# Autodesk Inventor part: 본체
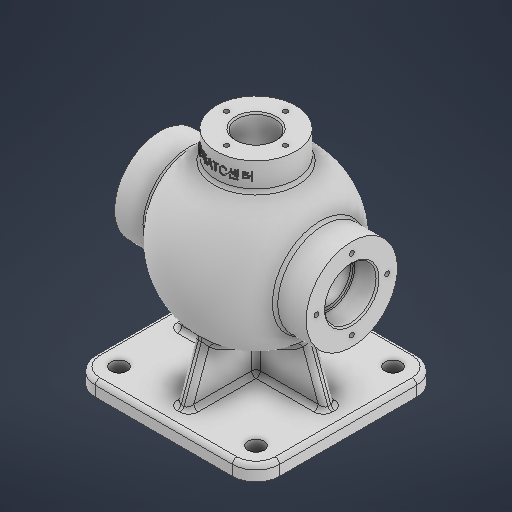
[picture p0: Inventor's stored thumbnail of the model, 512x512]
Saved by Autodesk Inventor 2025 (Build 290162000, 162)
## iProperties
Created: 2025-08
Part Number: 본체
Material: 일반
Document SubType Name: Modeling
Designer: infra14
Density: 1 g/cm^3
Appearance: 기본값
Author: infra14
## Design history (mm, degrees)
sketch "스케치1"
  geometry: L1 (-46.5, 62.5)-(46.5, 62.5); L2 (62.5, 46.5)-(62.5, -46.5); L3 (46.5, -62.5)-(-46.5, -62.5); L4 (-62.5, -46.5)-(-62.5, 46.5); L5 (-62.5, 62.5)-(62.5, -62.5); L6 (62.5, 62.5)-(-62.5, -62.5); A1 r 16 centre (46.5, 46.5) between (62.5, 46.5) and (46.5, 62.5); A2 r 16 centre (46.5, -46.5) between (46.5, -62.5) and (62.5, -46.5); A3 r 16 centre (-46.5, -46.5) between (-62.5, -46.5) and (-46.5, -62.5); A4 r 16 centre (-46.5, 46.5) between (-46.5, 62.5) and (-62.5, 46.5); 1 further point
  constraints: 12 end point, 8 point on circle, 8 point on line, 8 tangent, 4 centre point, 3 equal radius, 2 midpoint, 2 parallel, 1 horizontal, 1 perpendicular
  dimensions: "d0" = 125 distance of L6.end L5.start; "d1" = 125 distance of L5.end L6.end; "d2" = 16 radius of A1
extrude "돌출1" new body sketch "스케치1" distance "d3" = 10; taper "d4" = 0 deg
sketch "스케치2"
  geometry: L1 (46.5, 0)-(-46.5, 0) reference; L2 (65, 54)-(-65, 54); L3 (-65, 54)-(-65, 116); L4 (-65, 116)-(65, 116); L5 (65, 116)-(65, 54); L6 (65, 54)-(-65, 116); L7 (-65, 54)-(65, 116); L8 (65, 85)-(-65, 85); C1 r 54 at (0, 85); C2 r 44 at (0, 85); 6 further points
  constraints: 14 end point, 5 midpoint, 2 centre point, 2 parallel, 1 coincident, 1 horizontal, 1 perpendicular, 1 vertical alignment
  dimensions: "d5" = 108 diameter of C1; "d6" = 88 diameter of C2; "d7" = 85 distance from line of L1 C1.centre; "d8" = 62 distance between parallel lines of L2 L4; "d9" = 130 distance between parallel lines of L5 L3
revolve "회전1" stored, may be unused: angle "d10" = 90 deg
sketch "스케치3"
  geometry: L1 (-46.5, 10)-(46.5, 10) reference; L2 (50.5, 10)-(30.482, 65); L3 (30.482, 65)-(-30.482, 65); L4 (-30.482, 65)-(-50.5, 10); L5 (62.5, 0)-(62.5, 10) reference; L6 (-62.5, 0)-(-62.5, 10) reference; L7 (-46.5, 0)-(46.5, 0) reference; 1 further point
  constraints: 6 end point, 2 point on line, 1 parallel
  dimensions: "d11" = 12 distance from line of L5 L2.start; "d12" = 12 distance from line of L6 L4.end; "d13" = 20 deg angle of L5 L2; "d14" = 20 deg angle of L6 L4; "d15" = 65 distance between parallel lines of L7 L3
feature "리브1" sketch "스케치3" dims "d16" = 1, "d17" = 8, "d18" = 0, "d19" = 0, "d20" = 1, "d21" = 1
sketch "스케치4"
  geometry: L1 (10, -46.5)-(10, 46.5) reference; L2 (10, 50.5)-(65, 30.482); L3 (65, 30.482)-(65, -30.482); L4 (65, -30.482)-(10, -50.5); L5 (0, 62.5)-(10, 62.5) reference; L6 (0, -62.5)-(10, -62.5) reference; L7 (0, -46.5)-(0, 46.5) reference; 1 further point
  constraints: 6 end point, 2 point on line, 1 vertical
  dimensions: "d22" = 12 distance from line of L5 L2.start; "d23" = 12 distance from line of L6 L4.end; "d24" = 20 deg angle of L5 L2; "d25" = 20 deg angle of L6 L4; "d26" = 65 distance between parallel lines of L7 L3
feature "리브2" sketch "스케치4" dims "d27" = 1, "d28" = 8, "d29" = 0, "d30" = 0, "d31" = 1, "d32" = 1
sketch "스케치5"
  geometry: L1 (-65, 116)-(-65, 54) reference; L2 (-64, 102.5)-(-49.6, 102.5); L3 (-49, 101.9)-(-49, 100); L4 (-49, 100)-(-41.364, 100); L5 (-41.364, 100)-(-41.364, 85); L6 (-44.215, 116)-(-44.215, 54) reference; L7 (-41.364, 85)-(-65, 85); L8 (-65, 85)-(-65, 102.5); L9 (-65, 54)-(-65, 116) reference; L10 (-65, 103.5)-(-65, 116); L11 (-64, 102.5)-(-65, 103.5); A1 r 0.6 centre (-49.6, 101.9) between (-49, 101.9) and (-49.6, 102.5); 8 further points
  constraints: 16 end point, 5 point on line, 4 perpendicular, 2 point on circle, 2 tangent, 1 centre point, 1 collinear, 1 horizontal, 1 horizontal alignment, 1 midpoint, 1 parallel, 2 other
  dimensions: "d33" = 15 distance from line of L7 point (-45.182, 100); "d34" = 17.5 distance between parallel lines of L7 L2; "d35" = 16 distance of L8.end point (-49, 102.5); "d36" = 0.6 radius of A1; "d37" = 1 distance of L2.start L8.end; "d38" = 45 deg angle of L2 L11
revolve "회전2" sketch "스케치5" stored, may be unused: angle "d39" = 90 deg
sketch "스케치6"
  geometry: L1 (0, 0)-(0, 24); C1 r 18.5 at (0, 0) reference; C2 r 31 at (0, 0) reference; C3 r 15 at (0, 0) reference; 5 further points
  constraints: 2 end point, 1 coincident, 1 vertical, 5 other
  dimensions: "d40" = 24 distance of L1.start L1.end; "d43" = 360 deg dimension on C1.centre point (0, 24) (derived)
hole "구멍1" sketch "스케치6" at (0, 24), (-24, 0), (0, -24), (24, 0) diameter "d45" = 3.242; stored, may be unused: countersink angle "d49" = 90 deg, drill point angle "d51" = 118 deg; dims "d46" = 12, "d47" = 4, "d48" = 2, "d50" = 15
sketch "스케치7"
  geometry: C1 r 1.621 at (24, 0) reference; C2 r 1.621 at (0, -24) reference; C3 r 1.621 at (-24, 0) reference; C4 r 1.621 at (0, 24) reference; C5 r 18.5 at (0, 0) reference; C6 r 31 at (0, 0) reference; C7 r 15 at (0, 0) reference; C8 r 15 at (0, 0); 1 further point
  constraints: 1 centre point, 1 coincident
  dimensions: "d52" = 30 diameter of C8
extrude "돌출2" cut sketch "스케치7" extent not by distance; stored distance "d53" = 0; taper "d54" = 0 deg
sketch "스케치8"
  geometry: 1 further point
revolve "회전3" stored, may be unused: angle "d55" = 90 deg
node "작업 평면1"
sketch "스케치9"
  geometry: C1 r 27 at (0, 0); 1 further point
  constraints: 1 centre point, 1 coincident
  dimensions: "d57" = 54 diameter of C1
extrude "돌출3" join sketch "스케치9" stored distance "d58" = 10; taper "d59" = 0 deg
sketch "스케치10"
  geometry: C1 r 27 at (0, 0) reference; C2 r 13 at (0, 0); 1 further point
  constraints: 1 centre point, 1 coincident
  dimensions: "d60" = 26 diameter of C2
extrude "돌출4" cut sketch "스케치10" stored distance "d61" = 0; taper "d62" = 0 deg
sketch "스케치11"
  geometry: L1 (0, 0)-(0, -20); C1 r 13 at (0, 0) reference; 5 further points
  constraints: 2 end point, 1 coincident, 1 vertical, 5 other
  dimensions: "d63" = 20 distance of L1.start L1.end; "d66" = 360 deg dimension on point (0, 0) point (0, -20) (derived)
hole "구멍2" sketch "스케치11" at (0, -20), (20, 0), (0, 20), (-20, 0) diameter "d68" = 3.242; stored, may be unused: countersink angle "d72" = 90 deg, drill point angle "d74" = 118 deg; dims "d69" = 9, "d70" = 4, "d71" = 2, "d73" = 11
chamfer "모따기1" distance "d75" = 1; stored, may be unused: second distance "d76" = 2, angle "d77" = 45 deg
node "작업 평면2"
sketch "스케치12"
  geometry: L1 (-12.324, 143.035)-(12.324, 143.035); L2 (12.324, 143.035)-(12.324, 138.965); L3 (12.324, 138.965)-(-12.324, 138.965); L4 (-12.324, 138.965)-(-12.324, 143.035); L5 (-27, 150)-(27, 150) reference; 4 further points
  constraints: 3 midpoint, 1 vertical alignment, 2 other
  dimensions: "d79" = 9 distance from line of point (-12.324, 141) L5
feature "엠보싱1" sketch "스케치12" dims "d0" = 125, "d1" = 125, "d2" = 16, "d80" = 0.5, "d81" = 0
sketch "스케치13"
  geometry: L1 (-46.5, -46.5)-(46.5, -46.5); L2 (46.5, -46.5)-(46.5, 46.5); L3 (46.5, 46.5)-(-46.5, 46.5); L4 (-46.5, 46.5)-(-46.5, -46.5); L5 (-46.5, -46.5)-(46.5, 46.5); L6 (46.5, -46.5)-(-46.5, 46.5); C1 r 13 at (0, 0) reference; 5 further points
  constraints: 12 end point, 4 coincident, 2 midpoint, 2 parallel, 1 horizontal, 1 perpendicular
  dimensions: "d82" = 93 distance of L2.end L3.end; "d83" = 93 distance of L1.end L2.end
hole "구멍3" sketch "스케치13" at (-46.5, 46.5), (46.5, 46.5), (46.5, -46.5), (-46.5, -46.5) diameter "d84" = 11; stored, may be unused: countersink angle "d88" = 90 deg, drill point angle "d90" = 118 deg; dims "d85" = 9, "d86" = 4, "d87" = 2, "d89" = 11
fillet "모깎기1" dims "d91" = 3
fillet "모깎기2" dims "d92" = 3
fillet "모깎기3" dims "d93" = 3
fillet "모깎기4" dims "d94" = 3
feature "Ҍ耀Ҏ耀Ґ耀Ғ耀Ҕ耀Җ耀Ҙ耀Қ耀" dims "d0" = 125, "d1" = 125, "d2" = 16, "d3" = 10, "d4" = 0, "d5" = 108, "d6" = 88, "d7" = 85, "d8" = 62, "d9" = 130, "d10" = 90 deg, "d11" = 12, "d12" = 12, "d13" = 20 deg, "d14" = 20 deg, "d15" = 65, "d16" = 1, "d17" = 8, "d18" = 0, "d19" = 0, "d20" = 1, "d21" = 1, "d22" = 12, "d23" = 12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
node "솔리드1"
mirror "미러1"
node "투영된 루프1"
node "스케치 - 원형 패턴1" dims "d43" = 360 deg (derived)
node "투영된 루프2"
node "투영된 루프3"
node "스케치 - 원형 패턴2" dims "d66" = 360 deg (derived)
feature "A9D066F2-1C7D-4E18-AEED-F7BC21143FA4" dims "d84" = 11, "d85" = 9, "d86" = 4, "d87" = 2, "d88" = 90 deg, "d89" = 11, "d90" = 118 deg
